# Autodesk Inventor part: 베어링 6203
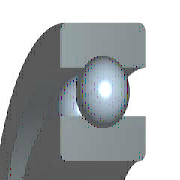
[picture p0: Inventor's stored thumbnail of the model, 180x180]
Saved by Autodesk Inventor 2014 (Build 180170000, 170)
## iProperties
IsCustomPart: 1
Company: 한국ATC센터
Created: 2009-02
Part Number: 베어링 6203
Material: 강, 연강
Description: 깊은 그루브 볼 베어링
Document SubType Name: Modeling
Standard: KS B 2023
Designer: KYOUNG IL JANG
Standards Organization: KS
Language: ko-KR
Size Designation: 6203 - 17 x 40 x 12
Categories: <MemberInstance><Categories><Category DisplayName="샤프트 부품" InternalName="7f7aeb1f-a693-4053-b835-cee3144e0d98" Mnemonic="SHFT"><Category DisplayName="베어링" Inter
Density: 1 g/cm^3
Appearance: 강철
Author: KYOUNG IL JANG
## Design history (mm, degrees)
sketch "스케치" dims "d0" = 5.98 (= -0.26 x WD + 0.26 x BD)
  geometry: L1 (3.01, 14.25)-(8.99, 14.25); L2 (6, 14.25)-(6, 11.26); L3 (6, 14.25)-(6, 17.24); L4 (3.778, 12.249)-(0, 12.249); L5 (0, 8.5)-(12, 8.5); L6 (3.778, 16.251)-(0, 16.251); L7 (0, 20)-(12, 20); L8 (12, 8.5)-(12, 12.249); L9 (8.222, 12.249)-(12, 12.249); L10 (8.222, 16.251)-(12, 16.251); L11 (12, 20)-(12, 16.251); L12 (-1.4, 0)-(8.4, 0) reference; L13 (0, -0.3)-(0, 5.3) reference
  constraints: 22 end point, 4 point on line, 2 collinear, 2 perpendicular, 2 symmetric about line, 1 midpoint, 1 parallel, 14 other
  dimensions: "d9" = 17 diameter of L5 L12 (= WD); "d11" = 40 diameter of L7 L12 (= BD); "d12" = 12 distance between parallel lines of L8 L13 (= KB); "d13" = 24.498 diameter of L9 L12 (= 0.326 x BD + 0.674 x WD)
revolve "본체" stored, may be unused: angle "d6" = 90 deg
revolve "볼" stored, may be unused: angle "d7" = 90 deg
pattern_circular "IDS_ARRAYBALL[SIMPL:T]" dims angle "d3" = 360 deg
body "Solid1"
fillet "모깎기1" dims "d1" = 0.6 (= KRS)
other parameters: "WD" = 17 [user parameter; used in 5 equation terms], "BD" = 40 [user parameter; used in 5 equation terms], "KB" = 12 [user parameter; used in 1 equation term], "KRS" = 0.6 [user parameter; used in 1 equation term], "d4" = 0, "d5" = 0, "d8" = 0, "d14" = 0, "d15" = 0, "BBA" = 0 [user parameter], "BC0" = 4750000 [user parameter], "BC" = 9560000 [user parameter], "WR" = 8.5 (= 0.5 x WD) [user parameter]
